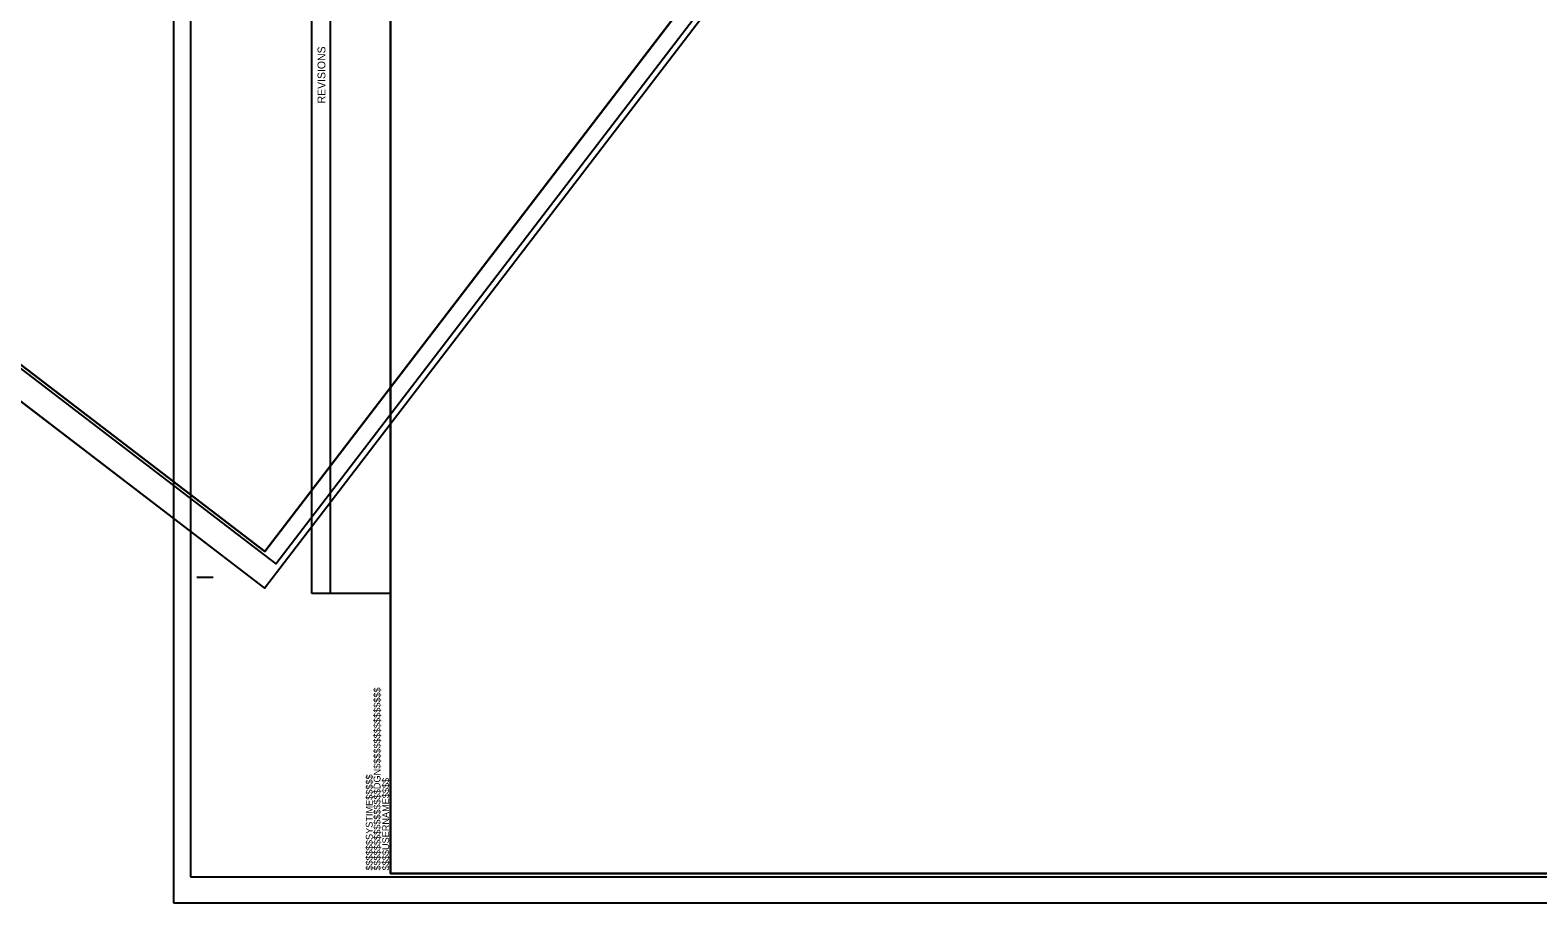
# Model space of a CAD drawing. Extents: x 1617779 to 1622406, y 896496 to 899510.
# Drawn here: x 1618935 to 1620092, y 897376 to 898046 of the extents above; entities that cross this region are included whole.
import ezdxf

# ---------------------------------------------------------------- set-up
doc = ezdxf.new("R2010")
doc.units = 0
for name, color, linetype in [('ControlPoints', 7, 'Continuous'), ('Exist Vertical Profile Ground Line', 7, 'Continuous'), ('Exist Vertical Profile Horizontal Axis Label Major', 7, 'Continuous'), ('Observations', 7, 'Continuous'), ('Prop Horizontal Alignment', 7, 'Continuous'), ('Setups', 7, 'Continuous')]:
    doc.layers.add(name, color=color, linetype=linetype)

msp = doc.modelspace()

# ---------------------------------------------------------------- linework, layer by layer
at = {"layer": 'ControlPoints'}
for points in [[(1617778.5, 898640.9), (1619115.1, 897617.3), (1619780.9, 898486.7), (1618444.3, 899510.3)], [(1619045.3, 897375.8), (1620728.8, 897375.8), (1620728.8, 898470.8), (1619045.3, 898470.8)]]:
    msp.add_lwpolyline(points, close=True, dxfattribs=at)
at = {"layer": 'Exist Vertical Profile Ground Line'}
msp.add_line((1619165.8, 897613.3), (1619165.8, 898403.9), dxfattribs=at)
msp.add_lwpolyline([(1619151.3, 897613.3), (1619151.3, 898403.9), (1619211.8, 898403.9), (1619211.8, 897613.3)], close=True, dxfattribs=at)
at = {"layer": 'Exist Vertical Profile Horizontal Axis Label Major'}
for p, q in [((1619063.3, 897625.8), (1619075.8, 897625.8)), ((1619211.8, 897398.3), (1619211.8, 897398.3))]:
    msp.add_line(p, q, dxfattribs=at)
for points in [[(1619753.7, 898479.1), (1618562.8, 899391.2), (1617924.4, 898557.6), (1619115.3, 897645.5)], [(1617924.4, 898557.6), (1618562.8, 899391.2), (1619594.9, 898600.8), (1619503.7, 898481.6), (1619662.5, 898360), (1619115.3, 897645.5)], [(1620711.8, 898448.3), (1619211.8, 898448.3), (1619211.8, 897398.3), (1620711.8, 897398.3)], [(1619211.8, 897398.3), (1619211.8, 898448.3), (1620511.7, 898448.3), (1620511.8, 898298.2), (1620711.8, 898298.2), (1620711.8, 897398.3)]]:
    msp.add_lwpolyline(points, close=True, dxfattribs=at)
at = {"layer": 'Observations'}
for points in [[(1618562.8, 899391.2), (1617924.4, 898557.6), (1619115.3, 897645.5), (1619625.1, 898311.3), (1619435.2, 898456.7), (1619563.8, 898624.6)], [(1619211.8, 898448.3), (1619211.8, 897398.3), (1620711.8, 897398.3), (1620711.8, 898236.8), (1620472.5, 898236.8), (1620472.5, 898448.3)]]:
    msp.add_lwpolyline(points, close=True, dxfattribs=at)
at = {"layer": 'Prop Horizontal Alignment'}
for p, q in [((1617778.5, 898640.9), (1619115.1, 897617.3)), ((1619045.3, 898470.8), (1619045.3, 897375.8)), ((1619045.3, 897375.8), (1620728.8, 897375.8))]:
    msp.add_line(p, q, dxfattribs=at)
at = {"layer": 'Setups'}
for points in [[(1617801, 898648.9), (1619123.7, 897636), (1619765.2, 898473.5), (1618442.5, 899486.5)], [(1619058.3, 897395.8), (1620724.3, 897395.8), (1620724.3, 898450.8), (1619058.3, 898450.8)]]:
    msp.add_lwpolyline(points, close=True, dxfattribs=at)

# ---------------------------------------------------------------- texts
at = {"layer": 'Exist Vertical Profile Ground Line'}
msp.add_text('REVISIONS', height=6, rotation=90, dxfattribs=at).set_placement((1619161.8, 897989.4))
at = {"layer": 'Exist Vertical Profile Horizontal Axis Label Major'}
for s, p in [('$$$$$$$$$$$$$$$$DGN$$$$$$$$$$$$$$$$', (1619204.1, 897400.6)), ('$$$$$$SYSTIME$$$$$', (1619198.1, 897400.6)), ('$$$$USERNAME$$$$', (1619210.7, 897400.7))]:
    msp.add_text(s, height=5.25, rotation=90, dxfattribs=at).set_placement(p)

doc.saveas('drawing.dxf')
